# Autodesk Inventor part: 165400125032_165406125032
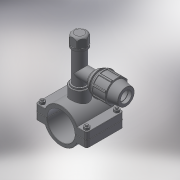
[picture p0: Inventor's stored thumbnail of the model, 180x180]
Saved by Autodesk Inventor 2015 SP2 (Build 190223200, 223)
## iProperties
Created: 2017-05
Part Number: 165400125032_165406125032
Material: Generic
Description: PLASSON TAPPER FOR PE+PVC PIPE 125-32
Document SubType Name: Modeling
Designer: KIM
Density: 1 g/cm^3
Appearance: Default
Author: KIM
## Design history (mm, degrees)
derived "16540.ipt"
feature "Solid1::16540.ipt"
feature "Solid2::16540.ipt"
tag "TaggingFeature1"
body "Solid1"
other parameters: "d0" = 137.5, "d1" = 184, "d2" = 62.5, "d3" = 125, "d4" = 124, "d5" = 0, "d6" = 9.2, "d7" = 184, "d8" = 0.1, "d10" = 0, "d11" = 1.25, "d14" = 50.6376, "d20" = 1.25, "d23" = 1.25, "d36" = 13, "d37" = 10.4, "d38" = 70.5, "d39" = 0, "d40" = 3, "d41" = 5, "d42" = 0, "d43" = 8, "d44" = 3, "d45" = 0, "d46" = 1.25, "d51" = 98, "d52" = 38.952, "d53" = 25, "d54" = 0, "d55" = 32, "d57" = 0, "d58" = 135, "d60" = 0, "d62" = 13, "d63" = 10.4, "d66" = 103.2, "d67" = 32, "d68" = 9.08333, "d69" = 21.8, "d70" = 64, "d71" = 48, "d72" = 1.55714, "d73" = 51.2, "d74" = 120 deg, "d75" = 48, "d76" = 10 deg, "d77" = 57.6, "d78" = 32.7, "d79" = 71, "d80" = 25.6, "d81" = 109, "d82" = 7.1, "d87" = 15.57143, "d90" = 59.52, "d91" = 35 deg, "d92" = 17.5 deg, "d94" = 0, "d96" = 360 deg, "d98" = 0.64, "d99" = 78.1, "d100" = 35.0568, "d101" = 135 deg, "d102" = 1.28, "d105" = 3.2, "d106" = 0, "d107" = 0.1, "d108" = 35.0568, "d109" = 42.8472, "d111" = 26.2, "d112" = 6.55, "d113" = 3.63333, "d116" = 0, "d117" = 38, "d118" = 21.8, "d119" = 0, "d121" = 131, "d122" = 58, "d_" = 125, "B_" = 32, "G_" = 38.952, "A_" = 98, "L_" = 184, "L_1" = 124, "l_2" = 25, "d_1" = 32, "E_" = 64, "l_" = 71, "H_" = 109, "H_1" = 58, "H_2" = 131
